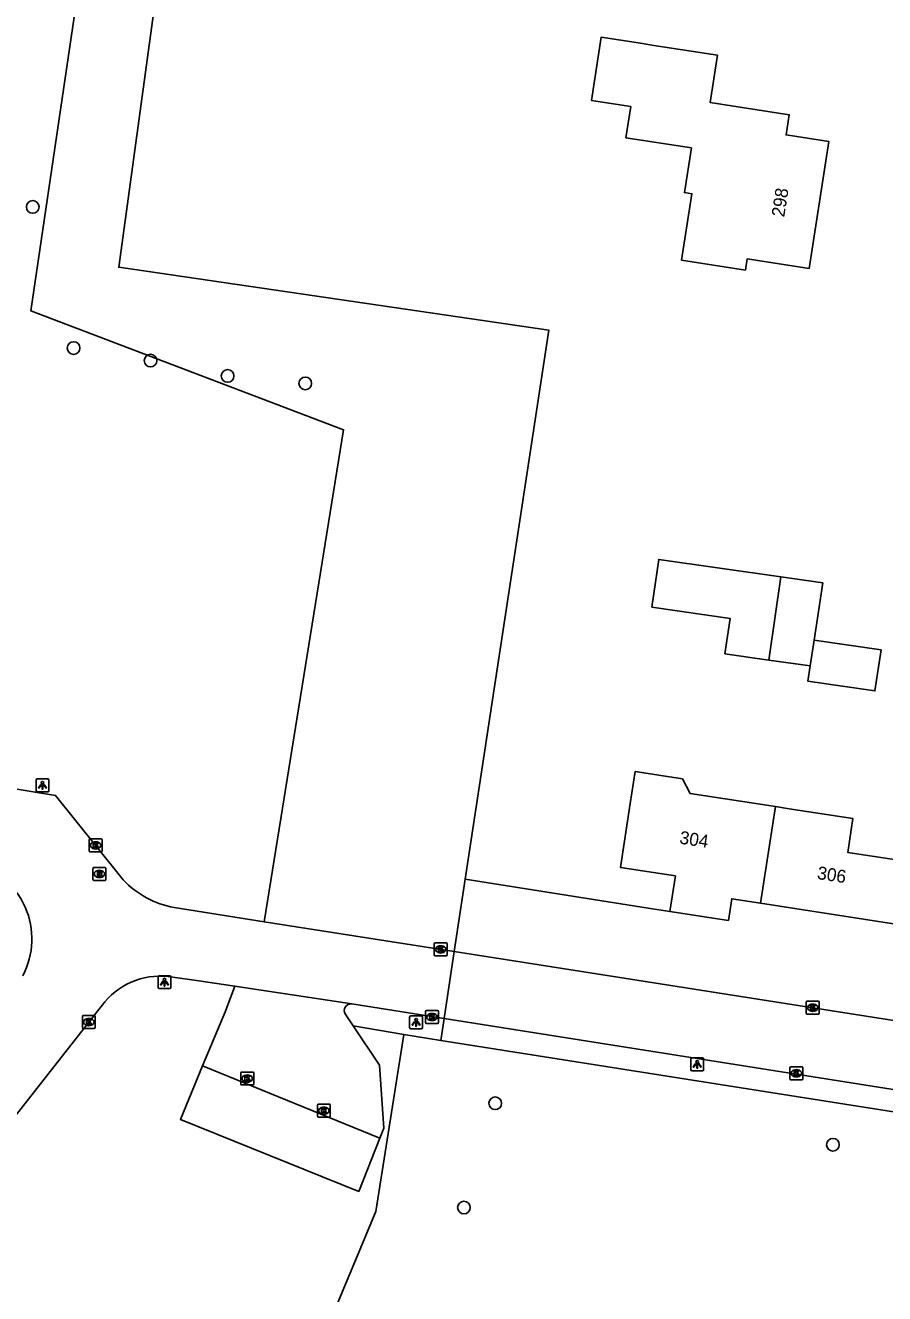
# Model space of a CAD drawing. Extents: x 161094 to 161705, y 379509 to 380907.
# Drawn here: x 161563.1 to 161629.6, y 380591.5 to 380689.7 of the extents above; entities that cross this region are included whole.
import ezdxf

# ---------------------------------------------------------------- set-up
doc = ezdxf.new("R2010")
doc.units = 0
for name, color, linetype in [('IMGEO_Boom', 7, 'Continuous'), ('IMGEO_Grasland_overig', 7, 'Continuous'), ('IMGEO_Hek', 7, 'Continuous'), ('IMGEO_Kolk', 7, 'Continuous'), ('IMGEO_Lichtpunt', 7, 'Continuous'), ('IMGEO_Loofbos', 7, 'Continuous'), ('IMGEO_Pand', 7, 'Continuous'), ('IMGEO_Pand_nummerreeks', 7, 'Continuous'), ('IMGEO_Parkeervlak_open', 7, 'Continuous'), ('IMGEO_Rijbaan_lokaal_open', 7, 'Continuous'), ('IMGEO_Rioolput', 7, 'Continuous')]:
    doc.layers.add(name, color=color, linetype=linetype)

msp = doc.modelspace()

# ---------------------------------------------------------------- linework, layer by layer
at = {"layer": 'IMGEO_Boom'}
for centre in [(161563.681, 380675.599), (161566.843, 380664.678), (161572.801, 380663.702), (161578.771, 380662.514), (161584.786, 380661.943), (161599.492, 380606.216), (161625.646, 380603), (161597.074, 380598.142)]:
    msp.add_circle(centre, 0.489, dxfattribs=at)
at = {"layer": 'IMGEO_Grasland_overig'}
for points in [[(161581.606, 380620.265), (161587.753, 380658.356), (161563.521, 380667.56), (161574.163, 380739.62)], [(161587.568, 380736.861), (161581.291, 380737.844), (161575.091, 380705.687), (161570.345, 380670.93), (161603.634, 380666.067), (161597.175, 380623.555), (161596.324, 380617.957)], [(161592.411, 380611.531), (161588.501, 380612.196)], [(161595.537, 380612.772), (161595.279, 380611.078)]]:
    msp.add_lwpolyline(points, dxfattribs=at)
at = {"layer": 'IMGEO_Hek'}
for points in [[(161597.175, 380623.555), (161603.634, 380666.067), (161570.345, 380670.93), (161575.091, 380705.687), (161581.291, 380737.844), (161587.568, 380736.861)], [(161597.175, 380623.555), (161596.324, 380617.957)], [(161611.339, 380621.328), (161597.175, 380623.555)], [(161613.027, 380621.063), (161611.339, 380621.328)], [(161596.324, 380617.957), (161595.537, 380612.772)], [(161595.537, 380612.772), (161595.279, 380611.078)], [(161595.279, 380611.078), (161592.411, 380611.531)], [(161643.59, 380603.451), (161595.279, 380611.078)]]:
    msp.add_lwpolyline(points, dxfattribs=at)
at = {"layer": 'IMGEO_Kolk'}
for p, q in [((161568.043, 380625.749), (161568.043, 380626.601)), ((161568.118, 380626.675), (161568.97, 380626.675)), ((161568.531, 380626.455), (161568.556, 380626.455)), ((161569.044, 380626.601), (161569.044, 380625.749)), ((161568.97, 380625.675), (161568.118, 380625.675)), ((161568.554, 380625.895), (161568.529, 380625.895)), ((161594.772, 380617.697), (161594.772, 380618.549)), ((161594.847, 380618.623), (161595.699, 380618.623)), ((161595.26, 380618.403), (161595.285, 380618.403)), ((161595.773, 380618.549), (161595.773, 380617.697)), ((161595.699, 380617.623), (161594.847, 380617.623)), ((161595.283, 380617.843), (161595.258, 380617.843)), ((161594.097, 380612.464), (161594.097, 380613.316)), ((161594.172, 380613.39), (161595.024, 380613.39)), ((161594.585, 380613.17), (161594.61, 380613.17)), ((161595.098, 380613.316), (161595.098, 380612.464)), ((161623.583, 380613.18), (161623.583, 380614.032)), ((161623.658, 380614.106), (161624.51, 380614.106)), ((161624.094, 380613.326), (161624.069, 380613.326)), ((161624.071, 380613.886), (161624.096, 380613.886)), ((161624.584, 380614.032), (161624.584, 380613.18)), ((161567.522, 380612.068), (161567.522, 380612.92)), ((161567.597, 380612.994), (161568.449, 380612.994)), ((161568.033, 380612.214), (161568.008, 380612.214)), ((161568.01, 380612.774), (161568.035, 380612.774)), ((161568.523, 380612.92), (161568.523, 380612.068)), ((161595.024, 380612.39), (161594.172, 380612.39)), ((161594.608, 380612.61), (161594.583, 380612.61)), ((161624.51, 380613.106), (161623.658, 380613.106)), ((161568.449, 380611.994), (161567.597, 380611.994)), ((161579.795, 380607.703), (161579.795, 380608.555)), ((161579.87, 380608.629), (161580.722, 380608.629)), ((161580.283, 380608.409), (161580.308, 380608.409)), ((161580.796, 380608.555), (161580.796, 380607.703)), ((161622.316, 380608.112), (161622.316, 380608.964)), ((161622.391, 380609.038), (161623.243, 380609.038)), ((161622.827, 380608.258), (161622.802, 380608.258)), ((161622.804, 380608.818), (161622.829, 380608.818)), ((161623.317, 380608.964), (161623.317, 380608.112)), ((161580.722, 380607.629), (161579.87, 380607.629)), ((161580.306, 380607.849), (161580.281, 380607.849)), ((161623.243, 380608.038), (161622.391, 380608.038)), ((161585.721, 380605.207), (161585.721, 380606.059)), ((161585.796, 380606.133), (161586.648, 380606.133)), ((161586.232, 380605.353), (161586.207, 380605.353)), ((161586.209, 380605.913), (161586.234, 380605.913)), ((161586.722, 380606.059), (161586.722, 380605.207)), ((161586.648, 380605.133), (161585.796, 380605.133))]:
    msp.add_line(p, q, dxfattribs=at)
for points in [[(161568.043, 380625.749), (161568.043, 380626.601)], [(161568.118, 380626.675), (161568.97, 380626.675)], [(161568.364, 380626.375), (161568.487, 380626.375), (161568.487, 380626.224), (161568.617, 380626.375), (161568.781, 380626.375), (161568.635, 380626.224), (161568.788, 380625.975), (161568.636, 380625.975), (161568.551, 380626.139), (161568.487, 380626.072), (161568.487, 380625.975), (161568.364, 380625.975), (161568.364, 380626.375)], [(161569.044, 380626.601), (161569.044, 380625.749)], [(161568.97, 380625.675), (161568.118, 380625.675)], [(161594.772, 380617.697), (161594.772, 380618.549)], [(161594.847, 380618.623), (161595.699, 380618.623)], [(161595.093, 380618.323), (161595.216, 380618.323), (161595.216, 380618.172), (161595.346, 380618.323), (161595.51, 380618.323), (161595.364, 380618.172), (161595.517, 380617.923), (161595.365, 380617.923), (161595.28, 380618.087), (161595.216, 380618.02), (161595.216, 380617.923), (161595.093, 380617.923), (161595.093, 380618.323)], [(161595.773, 380618.549), (161595.773, 380617.697)], [(161595.699, 380617.623), (161594.847, 380617.623)], [(161594.097, 380612.464), (161594.097, 380613.316)], [(161594.172, 380613.39), (161595.024, 380613.39)], [(161595.098, 380613.316), (161595.098, 380612.464)], [(161623.583, 380613.18), (161623.583, 380614.032)], [(161623.658, 380614.106), (161624.51, 380614.106)], [(161623.904, 380613.806), (161624.027, 380613.806), (161624.027, 380613.655), (161624.157, 380613.806), (161624.321, 380613.806), (161624.175, 380613.655), (161624.328, 380613.406), (161624.176, 380613.406), (161624.091, 380613.57), (161624.027, 380613.503), (161624.027, 380613.406), (161623.904, 380613.406), (161623.904, 380613.806)], [(161624.584, 380614.032), (161624.584, 380613.18)], [(161567.522, 380612.068), (161567.522, 380612.92)], [(161567.597, 380612.994), (161568.449, 380612.994)], [(161567.843, 380612.694), (161567.966, 380612.694), (161567.966, 380612.543), (161568.096, 380612.694), (161568.26, 380612.694), (161568.114, 380612.543), (161568.267, 380612.294), (161568.115, 380612.294), (161568.03, 380612.458), (161567.966, 380612.391), (161567.966, 380612.294), (161567.843, 380612.294), (161567.843, 380612.694)], [(161568.523, 380612.92), (161568.523, 380612.068)], [(161595.024, 380612.39), (161594.172, 380612.39)], [(161594.418, 380613.09), (161594.541, 380613.09), (161594.541, 380612.939), (161594.671, 380613.09), (161594.835, 380613.09), (161594.689, 380612.939), (161594.842, 380612.69), (161594.69, 380612.69), (161594.605, 380612.854), (161594.541, 380612.787), (161594.541, 380612.69), (161594.418, 380612.69), (161594.418, 380613.09)], [(161624.51, 380613.106), (161623.658, 380613.106)], [(161568.449, 380611.994), (161567.597, 380611.994)], [(161579.795, 380607.703), (161579.795, 380608.555)], [(161579.87, 380608.629), (161580.722, 380608.629)], [(161580.116, 380608.329), (161580.239, 380608.329), (161580.239, 380608.178), (161580.369, 380608.329), (161580.533, 380608.329), (161580.387, 380608.178), (161580.54, 380607.929), (161580.388, 380607.929), (161580.303, 380608.093), (161580.239, 380608.026), (161580.239, 380607.929), (161580.116, 380607.929), (161580.116, 380608.329)], [(161580.796, 380608.555), (161580.796, 380607.703)], [(161622.316, 380608.112), (161622.316, 380608.964)], [(161622.391, 380609.038), (161623.243, 380609.038)], [(161622.637, 380608.738), (161622.76, 380608.738), (161622.76, 380608.587), (161622.89, 380608.738), (161623.054, 380608.738), (161622.908, 380608.587), (161623.061, 380608.338), (161622.909, 380608.338), (161622.824, 380608.502), (161622.76, 380608.435), (161622.76, 380608.338), (161622.637, 380608.338), (161622.637, 380608.738)], [(161623.317, 380608.964), (161623.317, 380608.112)], [(161580.722, 380607.629), (161579.87, 380607.629)], [(161623.243, 380608.038), (161622.391, 380608.038)], [(161585.721, 380605.207), (161585.721, 380606.059)], [(161585.796, 380606.133), (161586.648, 380606.133)], [(161586.042, 380605.833), (161586.165, 380605.833), (161586.165, 380605.682), (161586.295, 380605.833), (161586.459, 380605.833), (161586.313, 380605.682), (161586.466, 380605.433), (161586.314, 380605.433), (161586.229, 380605.597), (161586.165, 380605.53), (161586.165, 380605.433), (161586.042, 380605.433), (161586.042, 380605.833)], [(161586.722, 380606.059), (161586.722, 380605.207)], [(161586.648, 380605.133), (161585.796, 380605.133)]]:
    msp.add_lwpolyline(points, dxfattribs=at)
for centre, start, end in [((161568.12, 380626.599), 91.55205, 178.44795), ((161568.12, 380626.599), 91.55205, 178.44795), ((161568.968, 380626.599), 1.55205, 88.44795), ((161568.968, 380626.599), 1.55205, 88.44795), ((161568.12, 380625.751), 181.55205, 268.44795), ((161568.12, 380625.751), 181.55205, 268.44795), ((161568.968, 380625.751), 271.55205, 358.44795), ((161568.968, 380625.751), 271.55205, 358.44795), ((161594.849, 380618.547), 91.55205, 178.44795), ((161594.849, 380618.547), 91.55205, 178.44795), ((161595.697, 380618.547), 1.55205, 88.44795), ((161595.697, 380618.547), 1.55205, 88.44795), ((161594.849, 380617.699), 181.55205, 268.44795), ((161594.849, 380617.699), 181.55205, 268.44795), ((161595.697, 380617.699), 271.55205, 358.44795), ((161595.697, 380617.699), 271.55205, 358.44795), ((161594.174, 380613.314), 91.55205, 178.44795), ((161594.174, 380613.314), 91.55205, 178.44795), ((161595.022, 380613.314), 1.55205, 88.44795), ((161595.022, 380613.314), 1.55205, 88.44795), ((161623.66, 380614.03), 91.55205, 178.44795), ((161623.66, 380614.03), 91.55205, 178.44795), ((161623.66, 380613.182), 181.55205, 268.44795), ((161623.66, 380613.182), 181.55205, 268.44795), ((161624.508, 380614.03), 1.55205, 88.44795), ((161624.508, 380614.03), 1.55205, 88.44795), ((161624.508, 380613.182), 271.55205, 358.44795), ((161624.508, 380613.182), 271.55205, 358.44795), ((161567.599, 380612.918), 91.55205, 178.44795), ((161567.599, 380612.918), 91.55205, 178.44795), ((161568.447, 380612.918), 1.55205, 88.44795), ((161568.447, 380612.918), 1.55205, 88.44795), ((161594.174, 380612.466), 181.55205, 268.44795), ((161594.174, 380612.466), 181.55205, 268.44795), ((161595.022, 380612.466), 271.55205, 358.44795), ((161595.022, 380612.466), 271.55205, 358.44795), ((161567.599, 380612.07), 181.55205, 268.44795), ((161567.599, 380612.07), 181.55205, 268.44795), ((161568.447, 380612.07), 271.55205, 358.44795), ((161568.447, 380612.07), 271.55205, 358.44795), ((161579.872, 380608.553), 91.55205, 178.44795), ((161579.872, 380608.553), 91.55205, 178.44795), ((161580.72, 380608.553), 1.55205, 88.44795), ((161580.72, 380608.553), 1.55205, 88.44795), ((161622.393, 380608.962), 91.55205, 178.44795), ((161622.393, 380608.962), 91.55205, 178.44795), ((161623.241, 380608.962), 1.55205, 88.44795), ((161623.241, 380608.962), 1.55205, 88.44795), ((161579.872, 380607.705), 181.55205, 268.44795), ((161579.872, 380607.705), 181.55205, 268.44795), ((161580.72, 380607.705), 271.55205, 358.44795), ((161580.72, 380607.705), 271.55205, 358.44795), ((161622.393, 380608.114), 181.55205, 268.44795), ((161622.393, 380608.114), 181.55205, 268.44795), ((161623.241, 380608.114), 271.55205, 358.44795), ((161623.241, 380608.114), 271.55205, 358.44795), ((161585.798, 380606.057), 91.55205, 178.44795), ((161585.798, 380606.057), 91.55205, 178.44795), ((161586.646, 380606.057), 1.55205, 88.44795), ((161586.646, 380606.057), 1.55205, 88.44795), ((161585.798, 380605.209), 181.55205, 268.44795), ((161585.798, 380605.209), 181.55205, 268.44795), ((161586.646, 380605.209), 271.55205, 358.44795), ((161586.646, 380605.209), 271.55205, 358.44795)]:
    msp.add_arc(centre, 0.0765, start, end, dxfattribs=at)
for centre, major_axis, ratio, start_param, end_param in [((161568.53, 380626.175), (-0.387, 0.002), 0.722429, 4.712389, 7.853982), ((161568.555, 380626.175), (-0.39, 0.002), 0.717154, 1.570796, 4.712389), ((161595.259, 380618.123), (-0.387, 0.002), 0.722429, 4.712389, 7.853982), ((161595.284, 380618.123), (-0.39, 0.002), 0.717154, 1.570796, 4.712389), ((161594.584, 380612.89), (-0.387, 0.002), 0.722429, 4.712389, 7.853982), ((161594.609, 380612.89), (-0.39, 0.002), 0.717154, 1.570796, 4.712389), ((161624.07, 380613.606), (-0.387, 0.002), 0.722429, 4.712389, 7.853982), ((161624.095, 380613.606), (-0.39, 0.002), 0.717154, 1.570796, 4.712389), ((161568.009, 380612.494), (-0.387, 0.002), 0.722429, 4.712389, 7.853982), ((161568.034, 380612.494), (-0.39, 0.002), 0.717154, 1.570796, 4.712389), ((161580.282, 380608.129), (-0.387, 0.002), 0.722429, 4.712389, 7.853982), ((161580.307, 380608.129), (-0.39, 0.002), 0.717154, 1.570796, 4.712389), ((161622.803, 380608.538), (-0.387, 0.002), 0.722429, 4.712389, 7.853982), ((161622.828, 380608.538), (-0.39, 0.002), 0.717154, 1.570796, 4.712389), ((161586.208, 380605.633), (-0.387, 0.002), 0.722429, 4.712389, 7.853982), ((161586.233, 380605.633), (-0.39, 0.002), 0.717154, 1.570796, 4.712389)]:
    msp.add_ellipse(centre, major_axis=major_axis, ratio=ratio, start_param=start_param, end_param=end_param, dxfattribs=at)
at = {"layer": 'IMGEO_Lichtpunt'}
for p, q in [((161563.938, 380631.233), (161563.938, 380630.426)), ((161563.938, 380631.233), (161563.938, 380630.426)), ((161564.84, 380631.328), (161564.032, 380631.328)), ((161564.84, 380631.328), (161564.032, 380631.328)), ((161564.934, 380630.426), (161564.934, 380631.233)), ((161564.934, 380630.426), (161564.934, 380631.233)), ((161564.032, 380630.332), (161564.84, 380630.332)), ((161564.032, 380630.332), (161564.84, 380630.332)), ((161573.386, 380615.989), (161573.386, 380615.182)), ((161573.386, 380615.989), (161573.386, 380615.182)), ((161574.288, 380616.084), (161573.48, 380616.084)), ((161574.288, 380616.084), (161573.48, 380616.084)), ((161574.382, 380615.182), (161574.382, 380615.989)), ((161574.382, 380615.182), (161574.382, 380615.989)), ((161573.48, 380615.088), (161574.288, 380615.088)), ((161573.48, 380615.088), (161574.288, 380615.088)), ((161592.868, 380612.88), (161592.868, 380612.073)), ((161592.868, 380612.88), (161592.868, 380612.073)), ((161593.77, 380612.975), (161592.962, 380612.975)), ((161593.77, 380612.975), (161592.962, 380612.975)), ((161593.864, 380612.073), (161593.864, 380612.88)), ((161593.864, 380612.073), (161593.864, 380612.88)), ((161592.962, 380611.979), (161593.77, 380611.979)), ((161592.962, 380611.979), (161593.77, 380611.979)), ((161614.638, 380609.624), (161614.638, 380608.817)), ((161614.638, 380609.624), (161614.638, 380608.817)), ((161615.54, 380609.719), (161614.732, 380609.719)), ((161615.54, 380609.719), (161614.732, 380609.719)), ((161615.634, 380608.817), (161615.634, 380609.624)), ((161615.634, 380608.817), (161615.634, 380609.624)), ((161614.732, 380608.723), (161615.54, 380608.723)), ((161614.732, 380608.723), (161615.54, 380608.723))]:
    msp.add_line(p, q, dxfattribs=at)
for points in [[(161564.312, 380630.897), (161564.351, 380630.869), (161564.163, 380630.607), (161564.125, 380630.634), (161564.312, 380630.897)], [(161564.414, 380630.849), (161564.461, 380630.849), (161564.461, 380630.527), (161564.414, 380630.527), (161564.414, 380630.849)], [(161564.524, 380630.869), (161564.562, 380630.896), (161564.749, 380630.634), (161564.71, 380630.606), (161564.524, 380630.869)], [(161573.76, 380615.653), (161573.799, 380615.625), (161573.611, 380615.363), (161573.573, 380615.39), (161573.76, 380615.653)], [(161573.862, 380615.605), (161573.909, 380615.605), (161573.909, 380615.283), (161573.862, 380615.283), (161573.862, 380615.605)], [(161573.972, 380615.625), (161574.01, 380615.652), (161574.197, 380615.39), (161574.158, 380615.362), (161573.972, 380615.625)], [(161593.242, 380612.544), (161593.281, 380612.516), (161593.093, 380612.254), (161593.055, 380612.281), (161593.242, 380612.544)], [(161593.344, 380612.496), (161593.391, 380612.496), (161593.391, 380612.174), (161593.344, 380612.174), (161593.344, 380612.496)], [(161593.454, 380612.516), (161593.492, 380612.543), (161593.679, 380612.281), (161593.64, 380612.253), (161593.454, 380612.516)], [(161615.012, 380609.288), (161615.051, 380609.26), (161614.863, 380608.998), (161614.825, 380609.025), (161615.012, 380609.288)], [(161615.114, 380609.24), (161615.161, 380609.24), (161615.161, 380608.918), (161615.114, 380608.918), (161615.114, 380609.24)], [(161615.224, 380609.26), (161615.262, 380609.287), (161615.449, 380609.025), (161615.41, 380608.997), (161615.224, 380609.26)]]:
    msp.add_lwpolyline(points, dxfattribs=at)
for centre in [(161564.437, 380631.031), (161573.885, 380615.787), (161593.367, 380612.678), (161615.137, 380609.422)]:
    msp.add_circle(centre, 0.0994, dxfattribs=at)
for centre, start, end in [((161564.032, 380631.233), 90, 180), ((161564.032, 380631.233), 90, 180), ((161564.84, 380631.233), 0, 90), ((161564.84, 380631.233), 0, 90), ((161564.032, 380630.426), 180, 270), ((161564.032, 380630.426), 180, 270), ((161564.84, 380630.426), 270, 0), ((161564.84, 380630.426), 270, 360), ((161573.48, 380615.989), 90, 180), ((161573.48, 380615.989), 90, 180), ((161573.48, 380615.182), 180, 270), ((161573.48, 380615.182), 180, 270), ((161574.288, 380615.989), 0, 90), ((161574.288, 380615.989), 0, 90), ((161574.288, 380615.182), 270, 0), ((161574.288, 380615.182), 270, 360), ((161592.962, 380612.88), 90, 180), ((161592.962, 380612.88), 90, 180), ((161593.77, 380612.88), 0, 90), ((161593.77, 380612.88), 0, 90), ((161592.962, 380612.073), 180, 270), ((161592.962, 380612.073), 180, 270), ((161593.77, 380612.073), 270, 0), ((161593.77, 380612.073), 270, 360), ((161614.732, 380609.624), 90, 180), ((161614.732, 380609.624), 90, 180), ((161615.54, 380609.624), 0, 90), ((161615.54, 380609.624), 0, 90), ((161614.732, 380608.817), 180, 270), ((161614.732, 380608.817), 180, 270), ((161615.54, 380608.817), 270, 0), ((161615.54, 380608.817), 270, 360)]:
    msp.add_arc(centre, 0.0946, start, end, dxfattribs=at)
at = {"layer": 'IMGEO_Loofbos'}
for points in [[(161570.511, 380550.506), (161590.25, 380597.842), (161592.411, 380611.531)], [(161595.279, 380611.078), (161592.411, 380611.531)], [(161648.105, 380598.425), (161642.981, 380599.406), (161643.59, 380603.451), (161595.279, 380611.078)]]:
    msp.add_lwpolyline(points, dxfattribs=at)
at = {"layer": 'IMGEO_Pand'}
for points in [[(161623.815, 380670.837), (161619.004, 380671.578), (161618.87, 380670.709), (161613.93, 380671.471), (161614.724, 380676.627), (161614.149, 380676.716), (161614.681, 380680.172), (161609.617, 380680.952), (161609.992, 380683.381), (161606.936, 380683.851), (161607.689, 380688.738), (161610.745, 380688.268), (161611.774, 380688.11), (161616.715, 380687.349), (161616.149, 380683.674), (161622.258, 380682.732), (161622.018, 380681.175), (161625.329, 380680.665), (161623.815, 380670.837)], [(161620.676, 380640.527), (161617.284, 380641.015), (161617.677, 380643.75), (161611.625, 380644.62), (161612.156, 380648.316), (161621.601, 380646.957)], [(161621.601, 380646.957), (161620.676, 380640.527)], [(161621.601, 380646.957), (161624.854, 380646.489), (161624.184, 380642.054)], [(161624.184, 380642.054), (161629.372, 380641.309), (161628.893, 380638.134), (161623.705, 380638.88), (161623.884, 380640.066)], [(161624.184, 380642.054), (161623.884, 380640.066)], [(161623.884, 380640.066), (161620.676, 380640.527)], [(161620.042, 380621.7), (161617.811, 380622.044), (161617.552, 380620.366), (161613.027, 380621.063), (161613.45, 380623.811), (161609.192, 380624.468), (161609.954, 380629.41), (161610.337, 380631.891), (161613.984, 380631.328), (161614.579, 380630.194), (161621.192, 380629.175)], [(161621.192, 380629.175), (161620.042, 380621.7)], [(161621.192, 380629.175), (161622.257, 380629.011), (161627.198, 380628.25), (161626.795, 380625.636), (161631.42, 380624.924), (161630.671, 380620.063), (161620.042, 380621.7)]]:
    msp.add_lwpolyline(points, dxfattribs=at)
at = {"layer": 'IMGEO_Parkeervlak_open'}
for points in [[(161576.82, 380609.108), (161578.612, 380613.331), (161579.34, 380615.27)], [(161588.501, 380612.196), (161587.879, 380613.128)], [(161588.501, 380612.196), (161590.525, 380609.166), (161590.859, 380604.28), (161590.553, 380603.521)], [(161590.553, 380603.521), (161588.931, 380599.387), (161575.115, 380604.968), (161576.82, 380609.108)], [(161576.82, 380609.108), (161590.553, 380603.521)]]:
    msp.add_lwpolyline(points, dxfattribs=at)
msp.add_arc((161588.319, 380613.391), 0.512, 82.88363, 210.9435, dxfattribs=at)
at = {"layer": 'IMGEO_Rijbaan_lokaal_open'}
for points in [[(161570.685, 380623.509), (161570.368, 380623.904), (161565.448, 380630.05), (161559.459, 380631.018)], [(161581.606, 380620.265), (161574.636, 380621.358)], [(161596.324, 380617.957), (161581.606, 380620.265)], [(161595.537, 380612.772), (161596.324, 380617.957)], [(161596.324, 380617.957), (161610.464, 380615.74), (161648.267, 380609.813), (161648.521, 380612.011), (161648.965, 380612.403), (161650.402, 380613.408), (161650.471, 380613.456)], [(161574.535, 380615.979), (161576.357, 380615.719), (161579.34, 380615.27)], [(161579.34, 380615.27), (161581.381, 380614.962), (161588.382, 380613.9)], [(161552.901, 380593.234), (161569.258, 380614.067)], [(161588.382, 380613.9), (161595.537, 380612.772)], [(161648.522, 380600.99), (161647.352, 380602.502), (161647.086, 380602.747), (161647.39, 380604.584), (161645.185, 380604.942), (161595.537, 380612.772)]]:
    msp.add_lwpolyline(points, dxfattribs=at)
for centre, radius, start, end in [((161557.52, 380618.937), 6.092, 332.12798, 75.35475), ((161575.986, 380628.543), 7.311, 223.51592, 259.35465), ((161573.574, 380610.393), 5.668, 80.23755, 139.59609)]:
    msp.add_arc(centre, radius, start, end, dxfattribs=at)
at = {"layer": 'IMGEO_Rioolput'}
for p, q in [((161568.346, 380623.543), (161568.346, 380624.395)), ((161568.421, 380624.469), (161569.273, 380624.469)), ((161568.834, 380624.249), (161568.859, 380624.249)), ((161569.347, 380624.395), (161569.347, 380623.543)), ((161569.273, 380623.469), (161568.421, 380623.469)), ((161568.857, 380623.689), (161568.832, 380623.689))]:
    msp.add_line(p, q, dxfattribs=at)
for points in [[(161568.346, 380623.543), (161568.346, 380624.395)], [(161568.421, 380624.469), (161569.273, 380624.469)], [(161568.935, 380624.167), (161568.683, 380624.169), (161568.683, 380623.769)], [(161568.861, 380624.088), (161568.807, 380624.088), (161568.807, 380624.007)], [(161568.807, 380624.007), (161568.859, 380624.007)], [(161569.347, 380624.395), (161569.347, 380623.543)], [(161569.273, 380623.469), (161568.421, 380623.469)], [(161568.683, 380623.769), (161568.807, 380623.769), (161568.807, 380623.931), (161568.818, 380623.931)], [(161568.865, 380623.902), (161568.936, 380623.769), (161569.076, 380623.769), (161569.011, 380623.895)]]:
    msp.add_lwpolyline(points, dxfattribs=at)
for centre, radius, start, end in [((161568.423, 380624.393), 0.0765, 91.55205, 178.44795), ((161568.423, 380624.393), 0.0765, 91.55205, 178.44795), ((161568.843, 380624.196), 0.19, 274.7715, 282.96867), ((161568.867, 380623.992), 0.0964, 77.00612, 93.18647), ((161568.881, 380624.049), 0.0378, 276.66336, 79.67722), ((161568.934, 380624.057), 0.109, 350.36119, 89.41601), ((161568.932, 380624.057), 0.112, 277.58423, 350.98172), ((161568.916, 380623.842), 0.108, 29.51342, 73.79051), ((161569.271, 380624.393), 0.0765, 1.55205, 88.44795), ((161569.271, 380624.393), 0.0765, 1.55205, 88.44795), ((161568.423, 380623.545), 0.0765, 181.55205, 268.44795), ((161568.423, 380623.545), 0.0765, 181.55205, 268.44795), ((161568.817, 380623.878), 0.0533, 26.02933, 88.69889), ((161569.271, 380623.545), 0.0765, 271.55205, 358.44795), ((161569.271, 380623.545), 0.0765, 271.55205, 358.44795)]:
    msp.add_arc(centre, radius, start, end, dxfattribs=at)
for centre, major_axis, ratio, start_param, end_param in [((161568.833, 380623.969), (-0.387, 0.002), 0.722429, 4.712389, 7.853982), ((161568.858, 380623.969), (-0.39, 0.002), 0.717154, 1.570796, 4.712389)]:
    msp.add_ellipse(centre, major_axis=major_axis, ratio=ratio, start_param=start_param, end_param=end_param, dxfattribs=at)

# ---------------------------------------------------------------- texts
at = {"layer": 'IMGEO_Pand_nummerreeks'}
for s, rotation, p in [('298', 81.24245, (161621.872, 380674.776)), ('304', 351.22856, (161613.721, 380626.318)), ('306', 351.24279, (161624.378, 380623.582))]:
    msp.add_text(s, height=1, rotation=rotation, dxfattribs=at).set_placement(p)

doc.saveas('drawing.dxf')
